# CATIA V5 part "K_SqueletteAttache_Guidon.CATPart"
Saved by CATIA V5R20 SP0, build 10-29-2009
Part number: Squelette_Attache_Guidon
Bounding box of the stored display mesh (mm): x -50 to 50, y -60 to 0, z -100 to 0
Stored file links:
  G:\Khaled_CFAO_2011\ST2M\ST2M_GR1\bmartinez\Khaled\CAD_ThinkMOTION\K_SqueletteAttache_Guidon.CATPart
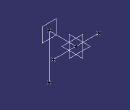
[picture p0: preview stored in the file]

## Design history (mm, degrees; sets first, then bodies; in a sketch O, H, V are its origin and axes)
Set1
  Point1: type OnCurve, Support Line1, RefPoint Point2, Length 50
  Line1: stored without definition
  Point2: stored without definition
  Point3: type OnCurve, Support Line2, RefPoint Point4, Length -50
  Line2: stored without definition
  Point4: stored without definition
  Line3: type PtPt, FirstPoint Point3, SecondPoint Point1
  Point5: type OnPlane, Support xy-plane, RefPoint Point6, H 0, V -60, Direction (1, 0, 0)
  Point6: stored without definition
  Line4: type PtPt, FirstPoint Point7, SecondPoint Point5
  Point7: stored without definition
  Plane1: type OffsetPt, RefPlane zx-plane, RefPoint Point5
  Point8: type OnPlane, Support Plane1, H 0, V -100, Direction (-1, 0, 0)
  Line5: type PtPt, FirstPoint Point5, SecondPoint Point8
Body1 (main body)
